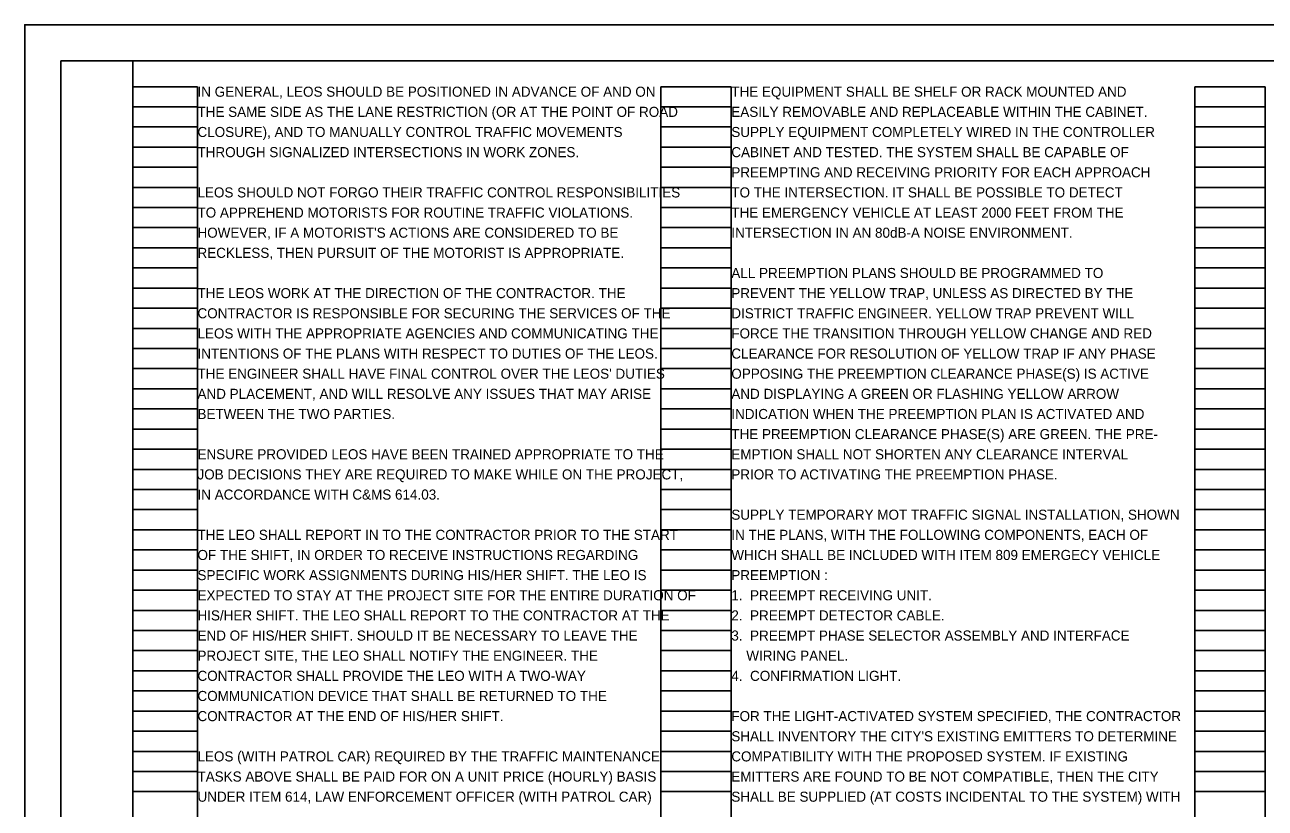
# Model space of a CAD drawing. Extents: x 0 to 34, y 0 to 22.
# Drawn here: x 0 to 17.24, y 11.11 to 22 of the extents above; entities that cross this region are included whole.
import ezdxf

# ---------------------------------------------------------------- set-up
doc = ezdxf.new("R2010")
doc.units = 0
for name, color, linetype in [('SH_Border', 7, 'Continuous'), ('SH_Cut_Line', 7, 'Continuous'), ('SH_Data', 7, 'Continuous'), ('SH_Text', 7, 'Continuous')]:
    doc.layers.add(name, color=color, linetype=linetype)

msp = doc.modelspace()

# ---------------------------------------------------------------- linework, layer by layer
at = {"layer": 'SH_Border'}
for points in [[(0.5, 21.5), (1.5, 21.5), (1.5, 0.5), (0.5, 0.5)], [(1.5, 21.5), (33.5, 21.5), (33.5, 0.5), (1.5, 0.5)]]:
    msp.add_lwpolyline(points, close=True, dxfattribs=at)
at = {"layer": 'SH_Cut_Line'}
msp.add_lwpolyline([(0, 0), (34, 0), (34, 22), (0, 22)], close=True, dxfattribs=at)
at = {"layer": 'SH_Data'}
for p, q in [((1.5, 0.98), (1.5, 21.14)), ((1.5, 21.14), (2.4, 21.14)), ((2.4, 0.98), (2.4, 21.14)), ((8.84, 0.98), (8.84, 21.14)), ((8.84, 21.14), (9.82, 21.14)), ((9.82, 0.98), (9.82, 21.14)), ((16.26, 0.98), (16.26, 21.14)), ((16.26, 21.14), (17.24, 21.14)), ((17.24, 0.98), (17.24, 21.14)), ((1.5, 20.86), (2.4, 20.86)), ((8.84, 20.86), (9.82, 20.86)), ((16.26, 20.86), (17.24, 20.86)), ((1.5, 20.58), (2.4, 20.58)), ((8.84, 20.58), (9.82, 20.58)), ((16.26, 20.58), (17.24, 20.58)), ((1.5, 20.3), (2.4, 20.3)), ((8.84, 20.3), (9.82, 20.3)), ((16.26, 20.3), (17.24, 20.3)), ((1.5, 20.02), (2.4, 20.02)), ((8.84, 20.02), (9.82, 20.02)), ((16.26, 20.02), (17.24, 20.02)), ((1.5, 19.74), (2.4, 19.74)), ((8.84, 19.74), (9.82, 19.74)), ((16.26, 19.74), (17.24, 19.74)), ((1.5, 19.46), (2.4, 19.46)), ((8.84, 19.46), (9.82, 19.46)), ((16.26, 19.46), (17.24, 19.46)), ((1.5, 19.18), (2.4, 19.18)), ((8.84, 19.18), (9.82, 19.18)), ((16.26, 19.18), (17.24, 19.18)), ((1.5, 18.9), (2.4, 18.9)), ((8.84, 18.9), (9.82, 18.9)), ((16.26, 18.9), (17.24, 18.9)), ((1.5, 18.62), (2.4, 18.62)), ((8.84, 18.62), (9.82, 18.62)), ((16.26, 18.62), (17.24, 18.62)), ((1.5, 18.34), (2.4, 18.34)), ((8.84, 18.34), (9.82, 18.34)), ((16.26, 18.34), (17.24, 18.34)), ((1.5, 18.06), (2.4, 18.06)), ((8.84, 18.06), (9.82, 18.06)), ((16.26, 18.06), (17.24, 18.06)), ((1.5, 17.78), (2.4, 17.78)), ((8.84, 17.78), (9.82, 17.78)), ((16.26, 17.78), (17.24, 17.78)), ((1.5, 17.5), (2.4, 17.5)), ((8.84, 17.5), (9.82, 17.5)), ((16.26, 17.5), (17.24, 17.5)), ((1.5, 17.22), (2.4, 17.22)), ((8.84, 17.22), (9.82, 17.22)), ((16.26, 17.22), (17.24, 17.22)), ((1.5, 16.94), (2.4, 16.94)), ((8.84, 16.94), (9.82, 16.94)), ((16.26, 16.94), (17.24, 16.94)), ((1.5, 16.66), (2.4, 16.66)), ((8.84, 16.66), (9.82, 16.66)), ((16.26, 16.66), (17.24, 16.66)), ((1.5, 16.38), (2.4, 16.38)), ((8.84, 16.38), (9.82, 16.38)), ((16.26, 16.38), (17.24, 16.38)), ((1.5, 16.1), (2.4, 16.1)), ((8.84, 16.1), (9.82, 16.1)), ((16.26, 16.1), (17.24, 16.1)), ((1.5, 15.82), (2.4, 15.82)), ((8.84, 15.82), (9.82, 15.82)), ((16.26, 15.82), (17.24, 15.82)), ((1.5, 15.54), (2.4, 15.54)), ((8.84, 15.54), (9.82, 15.54)), ((16.26, 15.54), (17.24, 15.54)), ((1.5, 15.26), (2.4, 15.26)), ((8.84, 15.26), (9.82, 15.26)), ((16.26, 15.26), (17.24, 15.26)), ((1.5, 14.98), (2.4, 14.98)), ((8.84, 14.98), (9.82, 14.98)), ((16.26, 14.98), (17.24, 14.98)), ((1.5, 14.7), (2.4, 14.7)), ((8.84, 14.7), (9.82, 14.7)), ((16.26, 14.7), (17.24, 14.7)), ((1.5, 14.42), (2.4, 14.42)), ((8.84, 14.42), (9.82, 14.42)), ((16.26, 14.42), (17.24, 14.42)), ((1.5, 14.14), (2.4, 14.14)), ((8.84, 14.14), (9.82, 14.14)), ((16.26, 14.14), (17.24, 14.14)), ((1.5, 13.86), (2.4, 13.86)), ((8.84, 13.86), (9.82, 13.86)), ((16.26, 13.86), (17.24, 13.86)), ((1.5, 13.58), (2.4, 13.58)), ((8.84, 13.58), (9.82, 13.58)), ((16.26, 13.58), (17.24, 13.58)), ((1.5, 13.3), (2.4, 13.3)), ((8.84, 13.3), (9.82, 13.3)), ((16.26, 13.3), (17.24, 13.3)), ((1.5, 13.02), (2.4, 13.02)), ((8.84, 13.02), (9.82, 13.02)), ((16.26, 13.02), (17.24, 13.02)), ((1.5, 12.74), (2.4, 12.74)), ((8.84, 12.74), (9.82, 12.74)), ((16.26, 12.74), (17.24, 12.74)), ((1.5, 12.46), (2.4, 12.46)), ((8.84, 12.46), (9.82, 12.46)), ((16.26, 12.46), (17.24, 12.46)), ((1.5, 12.18), (2.4, 12.18)), ((8.84, 12.18), (9.82, 12.18)), ((16.26, 12.18), (17.24, 12.18)), ((1.5, 11.9), (2.4, 11.9)), ((8.84, 11.9), (9.82, 11.9)), ((16.26, 11.9), (17.24, 11.9)), ((1.5, 11.62), (2.4, 11.62)), ((8.84, 11.62), (9.82, 11.62)), ((16.26, 11.62), (17.24, 11.62)), ((1.5, 11.34), (2.4, 11.34)), ((8.84, 11.34), (9.82, 11.34)), ((16.26, 11.34), (17.24, 11.34))]:
    msp.add_line(p, q, dxfattribs=at)

# ---------------------------------------------------------------- texts
at = {"layer": 'SH_Text'}
for s, p in [('IN GENERAL, LEOS SHOULD BE POSITIONED IN ADVANCE OF AND ON ', (2.4, 21)), ('THE EQUIPMENT SHALL BE SHELF OR RACK MOUNTED AND', (9.82, 21)), ('THE SAME SIDE AS THE LANE RESTRICTION (OR AT THE POINT OF ROAD ', (2.4, 20.72)), ('EASILY REMOVABLE AND REPLACEABLE WITHIN THE CABINET.', (9.82, 20.72)), ('CLOSURE), AND TO MANUALLY CONTROL TRAFFIC MOVEMENTS ', (2.4, 20.44)), ('SUPPLY EQUIPMENT COMPLETELY WIRED IN THE CONTROLLER', (9.82, 20.44)), ('THROUGH SIGNALIZED INTERSECTIONS IN WORK ZONES.', (2.4, 20.16)), ('CABINET AND TESTED. THE SYSTEM SHALL BE CAPABLE OF', (9.82, 20.16)), ('PREEMPTING AND RECEIVING PRIORITY FOR EACH APPROACH', (9.82, 19.88)), ('LEOS SHOULD NOT FORGO THEIR TRAFFIC CONTROL RESPONSIBILITIES ', (2.4, 19.6)), ('TO THE INTERSECTION. IT SHALL BE POSSIBLE TO DETECT', (9.82, 19.6)), ('TO APPREHEND MOTORISTS FOR ROUTINE TRAFFIC VIOLATIONS. ', (2.4, 19.32)), ('THE EMERGENCY VEHICLE AT LEAST 2000 FEET FROM THE', (9.82, 19.32)), ("HOWEVER, IF A MOTORIST'S ACTIONS ARE CONSIDERED TO BE ", (2.4, 19.04)), ('INTERSECTION IN AN 80dB-A NOISE ENVIRONMENT.', (9.82, 19.04)), ('RECKLESS, THEN PURSUIT OF THE MOTORIST IS APPROPRIATE.', (2.4, 18.76)), ('ALL PREEMPTION PLANS SHOULD BE PROGRAMMED TO', (9.82, 18.48)), ('THE LEOS WORK AT THE DIRECTION OF THE CONTRACTOR. THE ', (2.4, 18.2)), ('PREVENT THE YELLOW TRAP, UNLESS AS DIRECTED BY THE', (9.82, 18.2)), ('CONTRACTOR IS RESPONSIBLE FOR SECURING THE SERVICES OF THE ', (2.4, 17.92)), ('DISTRICT TRAFFIC ENGINEER. YELLOW TRAP PREVENT WILL', (9.82, 17.92)), ('LEOS WITH THE APPROPRIATE AGENCIES AND COMMUNICATING THE ', (2.4, 17.64)), ('FORCE THE TRANSITION THROUGH YELLOW CHANGE AND RED', (9.82, 17.64)), ('INTENTIONS OF THE PLANS WITH RESPECT TO DUTIES OF THE LEOS. ', (2.4, 17.36)), ('CLEARANCE FOR RESOLUTION OF YELLOW TRAP IF ANY PHASE', (9.82, 17.36)), ("THE ENGINEER SHALL HAVE FINAL CONTROL OVER THE LEOS' DUTIES ", (2.4, 17.08)), ('OPPOSING THE PREEMPTION CLEARANCE PHASE(S) IS ACTIVE', (9.82, 17.08)), ('AND PLACEMENT, AND WILL RESOLVE ANY ISSUES THAT MAY ARISE ', (2.4, 16.8)), ('AND DISPLAYING A GREEN OR FLASHING YELLOW ARROW', (9.82, 16.8)), ('BETWEEN THE TWO PARTIES.', (2.4, 16.52)), ('INDICATION WHEN THE PREEMPTION PLAN IS ACTIVATED AND', (9.82, 16.52)), ('THE PREEMPTION CLEARANCE PHASE(S) ARE GREEN. THE PRE-', (9.82, 16.24)), ('ENSURE PROVIDED LEOS HAVE BEEN TRAINED APPROPRIATE TO THE ', (2.4, 15.96)), ('EMPTION SHALL NOT SHORTEN ANY CLEARANCE INTERVAL', (9.82, 15.96)), ('JOB DECISIONS THEY ARE REQUIRED TO MAKE WHILE ON THE PROJECT, ', (2.4, 15.68)), ('PRIOR TO ACTIVATING THE PREEMPTION PHASE.', (9.82, 15.68)), ('IN ACCORDANCE WITH C&MS 614.03. ', (2.4, 15.4)), ('SUPPLY TEMPORARY MOT TRAFFIC SIGNAL INSTALLATION, SHOWN ', (9.82, 15.12)), ('THE LEO SHALL REPORT IN TO THE CONTRACTOR PRIOR TO THE START ', (2.4, 14.84)), ('IN THE PLANS, WITH THE FOLLOWING COMPONENTS, EACH OF', (9.82, 14.84)), ('OF THE SHIFT, IN ORDER TO RECEIVE INSTRUCTIONS REGARDING ', (2.4, 14.56)), ('WHICH SHALL BE INCLUDED WITH ITEM 809 EMERGECY VEHICLE ', (9.82, 14.56)), ('SPECIFIC WORK ASSIGNMENTS DURING HIS/HER SHIFT. THE LEO IS ', (2.4, 14.28)), ('PREEMPTION :', (9.82, 14.28)), ('EXPECTED TO STAY AT THE PROJECT SITE FOR THE ENTIRE DURATION OF ', (2.4, 14)), ('1.  PREEMPT RECEIVING UNIT.', (9.82, 14)), ('HIS/HER SHIFT. THE LEO SHALL REPORT TO THE CONTRACTOR AT THE ', (2.4, 13.72)), ('2.  PREEMPT DETECTOR CABLE.', (9.82, 13.72)), ('END OF HIS/HER SHIFT. SHOULD IT BE NECESSARY TO LEAVE THE ', (2.4, 13.44)), ('3.  PREEMPT PHASE SELECTOR ASSEMBLY AND INTERFACE', (9.82, 13.44)), ('PROJECT SITE, THE LEO SHALL NOTIFY THE ENGINEER. THE ', (2.4, 13.16)), ('    WIRING PANEL.', (9.82, 13.16)), ('CONTRACTOR SHALL PROVIDE THE LEO WITH A TWO-WAY ', (2.4, 12.88)), ('4.  CONFIRMATION LIGHT.', (9.82, 12.88)), ('COMMUNICATION DEVICE THAT SHALL BE RETURNED TO THE ', (2.4, 12.6)), ('CONTRACTOR AT THE END OF HIS/HER SHIFT.', (2.4, 12.32)), ('FOR THE LIGHT-ACTIVATED SYSTEM SPECIFIED, THE CONTRACTOR ', (9.82, 12.32)), ("SHALL INVENTORY THE CITY'S EXISTING EMITTERS TO DETERMINE ", (9.82, 12.04)), ('LEOS (WITH PATROL CAR) REQUIRED BY THE TRAFFIC MAINTENANCE ', (2.4, 11.76)), ('COMPATIBILITY WITH THE PROPOSED SYSTEM. IF EXISTING ', (9.82, 11.76)), ('TASKS ABOVE SHALL BE PAID FOR ON A UNIT PRICE (HOURLY) BASIS ', (2.4, 11.48)), ('EMITTERS ARE FOUND TO BE NOT COMPATIBLE, THEN THE CITY ', (9.82, 11.48)), ('UNDER ITEM 614, LAW ENFORCEMENT OFFICER (WITH PATROL CAR) ', (2.4, 11.2)), ('SHALL BE SUPPLIED (AT COSTS INCIDENTAL TO THE SYSTEM) WITH ', (9.82, 11.2))]:
    msp.add_text(s, height=0.14, dxfattribs=at).set_placement(p)

doc.saveas('drawing.dxf')
